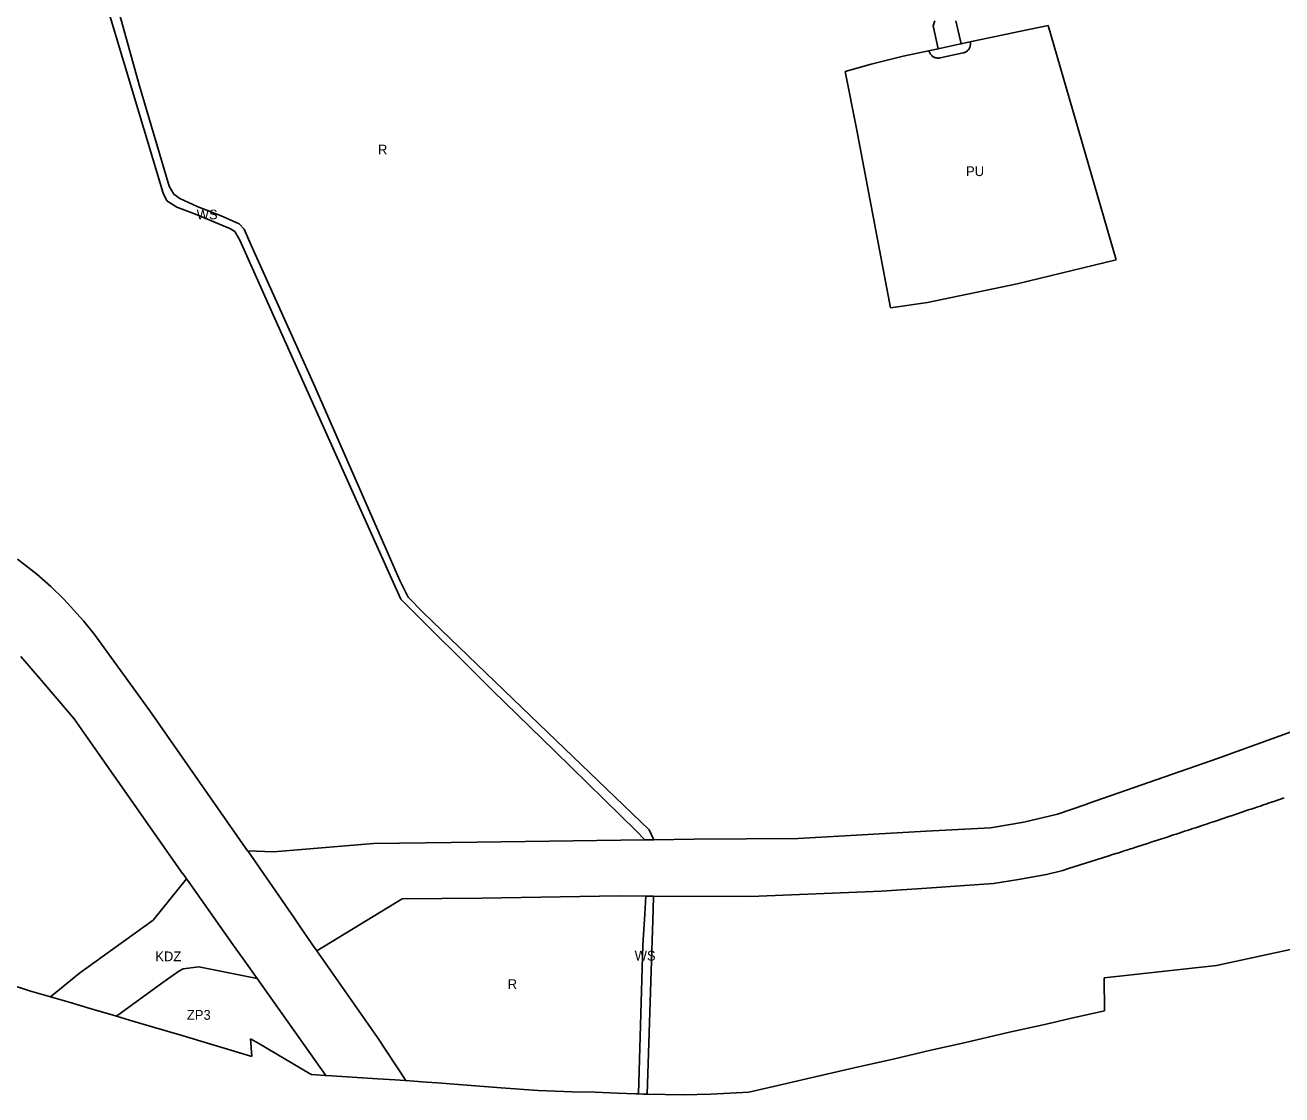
# Model space of a CAD drawing. Extents: x 7435758 to 7439981, y 5550649 to 5554049.
# Drawn here: x 7436435 to 7437107, y 5550649 to 5551221 of the extents above; entities that cross this region are included whole.
import ezdxf

# ---------------------------------------------------------------- set-up
doc = ezdxf.new("R2010")
doc.units = 0
for name, color, linetype in [('linie_rozgraniczające', 7, 'Continuous'), ('linie_zabudowy_nieprzekraczalne', 7, 'Continuous'), ('oznaczenia_przeznaczen', 7, 'Continuous')]:
    doc.layers.add(name, color=color, linetype=linetype)

msp = doc.modelspace()

# ---------------------------------------------------------------- linework, layer by layer
at = {"layer": 'linie_rozgraniczające'}
for p, q in [((7436459.7, 5551296.03), (7436509.03, 5551131.65)), ((7436496.23, 5551189.45), (7436466.37, 5551297.54)), ((7436921.72, 5551223.76), (7436920.85, 5551220.99)), ((7436935.81, 5551211.44), (7436933.05, 5551223.72)), ((7436920.85, 5551220.99), (7436923.56, 5551208.82)), ((7436967.82, 5551218.31), (7436938.84, 5551212.09)), ((7436982.44, 5551221.26), (7436967.82, 5551218.31)), ((7437018.71, 5551095.99), (7436982.44, 5551221.26)), ((7436923.56, 5551208.82), (7436904.82, 5551204.81)), ((7436923.56, 5551208.82), (7436923.98, 5551208.91)), ((7436923.98, 5551208.91), (7436925.08, 5551209.15)), ((7436925.08, 5551209.15), (7436926.84, 5551209.52)), ((7436926.84, 5551209.52), (7436934.77, 5551211.22)), ((7436934.77, 5551211.22), (7436935.81, 5551211.44)), ((7436936.37, 5551211.56), (7436935.81, 5551211.44)), ((7436938.84, 5551212.09), (7436936.37, 5551211.56)), ((7436901.89, 5551204.18), (7436887.77, 5551200.6)), ((7436904.82, 5551204.81), (7436901.89, 5551204.18)), ((7436887.77, 5551200.6), (7436873.73, 5551196.68)), ((7436873.73, 5551196.68), (7436879.85, 5551166.15)), ((7436512.13, 5551135.3), (7436496.23, 5551189.45)), ((7436879.85, 5551166.15), (7436898.01, 5551070.33)), ((7436514.79, 5551131.05), (7436512.13, 5551135.3)), ((7436509.03, 5551131.65), (7436510.99, 5551127.57)), ((7436510.99, 5551127.57), (7436516.32, 5551124.05)), ((7436518, 5551128.69), (7436514.79, 5551131.05)), ((7436527.1, 5551124.49), (7436518, 5551128.69)), ((7436516.32, 5551124.05), (7436526.23, 5551120.3)), ((7436539.96, 5551119.51), (7436527.1, 5551124.49)), ((7436526.23, 5551120.3), (7436544.6, 5551112.64)), ((7436549.69, 5551115.13), (7436539.96, 5551119.51)), ((7436552.29, 5551112.33), (7436549.69, 5551115.13)), ((7436544.6, 5551112.64), (7436547.36, 5551111.09)), ((7436547.36, 5551111.09), (7436550.04, 5551106.43)), ((7436555.95, 5551104.07), (7436552.29, 5551112.33)), ((7436550.04, 5551106.43), (7436567.16, 5551068.1)), ((7436589.47, 5551029.78), (7436555.95, 5551104.07)), ((7436965.75, 5551083.06), (7437018.71, 5551095.99)), ((7436917.85, 5551073.13), (7436965.75, 5551083.06)), ((7436567.16, 5551068.1), (7436595.91, 5551004.2)), ((7436898.01, 5551070.33), (7436917.85, 5551073.13)), ((7436623.1, 5550953), (7436589.47, 5551029.78)), ((7436595.91, 5551004.2), (7436631.06, 5550925.61)), ((7436635.68, 5550924.45), (7436623.1, 5550953)), ((7436431, 5550935.96), (7436441.38, 5550927.82)), ((7436441.38, 5550927.82), (7436448.86, 5550921.33)), ((7436448.86, 5550921.33), (7436455.79, 5550914.51)), ((7436631.06, 5550925.61), (7436636.08, 5550914.4)), ((7436639.98, 5550915.49), (7436635.68, 5550924.45)), ((7436455.79, 5550914.51), (7436466.44, 5550902.86)), ((7436636.08, 5550914.4), (7436685.18, 5550865.64)), ((7436648.21, 5550907.1), (7436639.98, 5550915.49)), ((7436705.45, 5550852.04), (7436648.21, 5550907.1)), ((7436466.44, 5550902.86), (7436472.26, 5550895.52)), ((7436472.26, 5550895.52), (7436501.9, 5550854.69)), ((7436443.93, 5550871.08), (7436432.85, 5550883.86)), ((7436461.44, 5550850.41), (7436443.93, 5550871.08)), ((7436685.18, 5550865.64), (7436718.46, 5550833.16)), ((7436501.9, 5550854.69), (7436554.03, 5550779.92)), ((7436768.94, 5550791.2), (7436705.45, 5550852.04)), ((7437148.56, 5550856.57), (7437073.01, 5550829.36)), ((7436473.84, 5550832.63), (7436461.44, 5550850.41)), ((7436484.73, 5550817.12), (7436473.84, 5550832.63)), ((7436718.46, 5550833.16), (7436762.12, 5550790.41)), ((7437073.01, 5550829.36), (7437003.86, 5550805.18)), ((7436519.37, 5550767.78), (7436484.73, 5550817.12)), ((7437003.86, 5550805.18), (7437002.47, 5550804.74)), ((7437097.01, 5550804.3), (7437099.33, 5550805.09)), ((7437099.33, 5550805.09), (7437100.05, 5550805.33)), ((7437100.05, 5550805.33), (7437102.43, 5550806.14)), ((7437102.43, 5550806.14), (7437103.1, 5550806.37)), ((7437103.1, 5550806.37), (7437105.53, 5550807.21)), ((7437105.53, 5550807.21), (7437106.15, 5550807.42)), ((7437106.15, 5550807.42), (7437108.65, 5550808.27)), ((7436987.39, 5550799.52), (7436969.37, 5550795.22)), ((7437002.47, 5550804.74), (7436987.39, 5550799.52)), ((7437077.88, 5550797.83), (7437078.97, 5550798.2)), ((7437078.97, 5550798.2), (7437080.92, 5550798.85)), ((7437080.92, 5550798.85), (7437081.96, 5550799.2)), ((7437081.96, 5550799.2), (7437083.96, 5550799.88)), ((7437083.96, 5550799.88), (7437084.95, 5550800.21)), ((7437084.95, 5550800.21), (7437087.02, 5550800.91)), ((7437087.02, 5550800.91), (7437087.95, 5550801.23)), ((7437087.95, 5550801.23), (7437090.08, 5550801.94)), ((7437090.08, 5550801.94), (7437090.97, 5550802.24)), ((7437090.97, 5550802.24), (7437093.15, 5550802.99)), ((7437093.15, 5550802.99), (7437093.99, 5550803.27)), ((7437093.99, 5550803.27), (7437096.24, 5550804.03)), ((7437096.24, 5550804.03), (7437097.01, 5550804.3)), ((7436951.63, 5550792.22), (7436917.11, 5550790.34)), ((7436969.37, 5550795.22), (7436951.63, 5550792.22)), ((7437058.27, 5550791.3), (7437059.81, 5550791.81)), ((7437059.81, 5550791.81), (7437061.21, 5550792.27)), ((7437061.21, 5550792.27), (7437062.8, 5550792.8)), ((7437062.8, 5550792.8), (7437064.15, 5550793.25)), ((7437064.15, 5550793.25), (7437065.8, 5550793.8)), ((7437065.8, 5550793.8), (7437067.1, 5550794.23)), ((7437067.1, 5550794.23), (7437068.81, 5550794.8)), ((7437068.81, 5550794.8), (7437070.06, 5550795.22)), ((7437070.06, 5550795.22), (7437071.82, 5550795.8)), ((7437071.82, 5550795.8), (7437073.02, 5550796.2)), ((7437073.02, 5550796.2), (7437074.85, 5550796.81)), ((7437074.85, 5550796.81), (7437075.99, 5550797.2)), ((7437075.99, 5550797.2), (7437077.88, 5550797.83)), ((7436766.65, 5550785.74), (7436676.99, 5550784.49)), ((7436762.12, 5550790.41), (7436766.65, 5550785.74)), ((7436766.65, 5550785.74), (7436771.44, 5550785.81)), ((7436771.44, 5550785.81), (7436768.94, 5550791.2)), ((7436793.04, 5550786.11), (7436771.44, 5550785.81)), ((7436848.73, 5550786.59), (7436793.04, 5550786.11)), ((7436917.11, 5550790.34), (7436848.73, 5550786.59)), ((7437036.12, 5550784.05), (7437037.92, 5550784.64)), ((7437037.92, 5550784.64), (7437039.06, 5550785.01)), ((7437039.06, 5550785.01), (7437040.81, 5550785.58)), ((7437040.81, 5550785.58), (7437042, 5550785.97)), ((7437042, 5550785.97), (7437043.7, 5550786.52)), ((7437043.7, 5550786.52), (7437044.95, 5550786.93)), ((7437044.95, 5550786.93), (7437046.6, 5550787.47)), ((7437046.6, 5550787.47), (7437047.91, 5550787.9)), ((7437047.91, 5550787.9), (7437049.51, 5550788.42)), ((7437049.51, 5550788.42), (7437050.87, 5550788.87)), ((7437050.87, 5550788.87), (7437052.42, 5550789.38)), ((7437052.42, 5550789.38), (7437053.84, 5550789.84)), ((7437053.84, 5550789.84), (7437055.35, 5550790.34)), ((7437055.35, 5550790.34), (7437056.82, 5550790.82)), ((7437056.82, 5550790.82), (7437058.27, 5550791.3)), ((7436554.03, 5550779.92), (7436554.37, 5550779.91)), ((7436554.37, 5550779.91), (7436554.36, 5550779.86)), ((7436554.36, 5550779.86), (7436579.12, 5550744.04)), ((7436568.1, 5550779.29), (7436554.37, 5550779.91)), ((7436621.47, 5550783.86), (7436568.1, 5550779.29)), ((7436676.99, 5550784.49), (7436621.47, 5550783.86)), ((7437015.75, 5550777.51), (7437018.64, 5550778.43)), ((7437018.64, 5550778.43), (7437019.63, 5550778.74)), ((7437019.63, 5550778.74), (7437021.54, 5550779.36)), ((7437021.54, 5550779.36), (7437023.58, 5550780.01)), ((7437023.58, 5550780.01), (7437024.44, 5550780.29)), ((7437024.44, 5550780.29), (7437026.43, 5550780.93)), ((7437026.43, 5550780.93), (7437027.35, 5550781.22)), ((7437027.35, 5550781.22), (7437029.3, 5550781.85)), ((7437029.3, 5550781.85), (7437030.27, 5550782.16)), ((7437030.27, 5550782.16), (7437032.17, 5550782.77)), ((7437032.17, 5550782.77), (7437033.19, 5550783.11)), ((7437033.19, 5550783.11), (7437035.04, 5550783.7)), ((7437035.04, 5550783.7), (7437036.12, 5550784.05)), ((7436993.21, 5550770.38), (7437014.36, 5550777.07)), ((7437014.36, 5550777.07), (7437014.91, 5550777.24)), ((7437014.91, 5550777.24), (7437015.46, 5550777.42)), ((7437015.46, 5550777.42), (7437015.72, 5550777.5)), ((7437015.72, 5550777.5), (7437015.75, 5550777.51)), ((7436521.56, 5550764.97), (7436503.68, 5550742.8)), ((7436519.57, 5550767.79), (7436519.37, 5550767.78)), ((7436521.56, 5550764.97), (7436519.57, 5550767.79)), ((7436522.05, 5550764.27), (7436521.56, 5550764.97)), ((7436953.09, 5550762.52), (7436966.48, 5550764.65)), ((7436966.48, 5550764.65), (7436981.51, 5550767.19)), ((7436981.51, 5550767.19), (7436990.22, 5550769.43)), ((7436990.22, 5550769.43), (7436993.21, 5550770.38)), ((7436523.85, 5550761.72), (7436522.05, 5550764.27)), ((7436545.1, 5550731.53), (7436523.85, 5550761.72)), ((7436823.12, 5550755.47), (7436893.19, 5550758.31)), ((7436893.19, 5550758.31), (7436917.51, 5550759.89)), ((7436917.51, 5550759.89), (7436953.09, 5550762.52)), ((7436591.13, 5550726.48), (7436636.87, 5550754.2)), ((7436636.87, 5550754.2), (7436679.42, 5550754.59)), ((7436679.42, 5550754.59), (7436752.93, 5550755.79)), ((7436752.93, 5550755.79), (7436767.22, 5550755.72)), ((7436767.22, 5550755.72), (7436766.62, 5550746.07)), ((7436771.2, 5550755.71), (7436767.22, 5550755.72)), ((7436771.09, 5550748.33), (7436771.2, 5550755.71)), ((7436771.2, 5550755.71), (7436823.12, 5550755.47)), ((7436766.62, 5550746.07), (7436765.63, 5550729.42)), ((7436767.84, 5550649.78), (7436771.09, 5550748.33)), ((7436503.68, 5550742.8), (7436471.83, 5550719.96)), ((7436579.12, 5550744.04), (7436579.85, 5550742.98)), ((7436579.85, 5550742.98), (7436582, 5550739.87)), ((7436582, 5550739.87), (7436588.56, 5550730.13)), ((7436546.66, 5550729.32), (7436545.1, 5550731.53)), ((7436547.18, 5550728.58), (7436546.66, 5550729.32)), ((7436552.6, 5550720.95), (7436547.18, 5550728.58)), ((7436588.56, 5550730.13), (7436591.13, 5550726.48)), ((7436591.13, 5550726.48), (7436623.68, 5550680.13)), ((7436765.63, 5550729.42), (7436763.27, 5550649.93)), ((7437126.08, 5550730.18), (7437072.37, 5550718.54)), ((7436471.83, 5550719.96), (7436464.16, 5550714.46)), ((7436528.04, 5550717.83), (7436519.72, 5550716.78)), ((7436559.24, 5550711.59), (7436528.04, 5550717.83)), ((7436559.24, 5550711.59), (7436552.6, 5550720.95)), ((7437072.37, 5550718.54), (7437012.36, 5550711.98)), ((7436464.16, 5550714.46), (7436448.78, 5550701.87)), ((7436517.33, 5550715.54), (7436508.22, 5550709.11)), ((7436519.72, 5550716.78), (7436517.33, 5550715.54)), ((7436596.06, 5550659.71), (7436559.24, 5550711.59)), ((7437012.36, 5550711.98), (7437012.6, 5550694.43)), ((7436437.48, 5550705.09), (7436426.03, 5550708.86)), ((7436448.78, 5550701.87), (7436437.48, 5550705.09)), ((7436508.22, 5550709.11), (7436484.06, 5550691.46)), ((7436458.65, 5550699.06), (7436448.78, 5550701.87)), ((7436470.53, 5550695.46), (7436458.65, 5550699.06)), ((7436482.32, 5550691.97), (7436470.53, 5550695.46)), ((7436484.06, 5550691.46), (7436482.32, 5550691.97)), ((7436491, 5550689.42), (7436484.06, 5550691.46)), ((7436998.96, 5550691.37), (7436994.79, 5550690.4)), ((7437012.6, 5550694.43), (7436998.96, 5550691.37)), ((7436504.36, 5550685.49), (7436491, 5550689.42)), ((7436517.96, 5550681.46), (7436504.36, 5550685.49)), ((7436981.27, 5550687.24), (7436960.14, 5550682.66)), ((7436994.79, 5550690.4), (7436981.27, 5550687.24)), ((7436556.42, 5550670.02), (7436517.96, 5550681.46)), ((7436560.24, 5550676.84), (7436555.66, 5550679.37)), ((7436555.66, 5550679.37), (7436556.42, 5550670.02)), ((7436623.68, 5550680.13), (7436638.75, 5550657.08)), ((7436937.4, 5550677.32), (7436919.6, 5550673.24)), ((7436960.14, 5550682.66), (7436937.4, 5550677.32)), ((7436587.3, 5550660.9), (7436560.24, 5550676.84)), ((7436919.6, 5550673.24), (7436899.53, 5550668.59)), ((7436880.99, 5550664.38), (7436853.13, 5550657.96)), ((7436899.53, 5550668.59), (7436880.99, 5550664.38)), ((7436588.27, 5550660.33), (7436587.3, 5550660.9)), ((7436595.74, 5550659.73), (7436588.27, 5550660.33)), ((7436596.06, 5550659.71), (7436595.74, 5550659.73)), ((7436599.21, 5550659.58), (7436596.06, 5550659.71)), ((7436623.56, 5550658.05), (7436599.21, 5550659.58)), ((7436633.12, 5550657.46), (7436623.56, 5550658.05)), ((7436638.52, 5550657.1), (7436633.12, 5550657.46)), ((7436638.75, 5550657.08), (7436638.52, 5550657.1)), ((7436643.09, 5550656.7), (7436638.75, 5550657.08)), ((7436853.13, 5550657.96), (7436840.19, 5550654.99)), ((7436649.83, 5550656.19), (7436643.09, 5550656.7)), ((7436655.54, 5550655.77), (7436649.83, 5550656.19)), ((7436689.81, 5550653.16), (7436655.54, 5550655.77)), ((7436709.52, 5550651.69), (7436689.81, 5550653.16)), ((7436727.81, 5550651.09), (7436709.52, 5550651.69)), ((7436740.02, 5550650.86), (7436727.81, 5550651.09)), ((7436751.77, 5550650.28), (7436740.02, 5550650.86)), ((7436762.02, 5550649.99), (7436751.77, 5550650.28)), ((7436822.3, 5550650.94), (7436801.97, 5550649.86)), ((7436840.19, 5550654.99), (7436822.3, 5550650.94)), ((7436763.27, 5550649.93), (7436762.02, 5550649.99)), ((7436765.92, 5550649.81), (7436763.27, 5550649.93)), ((7436767.84, 5550649.78), (7436765.92, 5550649.81)), ((7436787.23, 5550649.42), (7436767.84, 5550649.78)), ((7436801.97, 5550649.86), (7436787.23, 5550649.42))]:
    msp.add_line(p, q, dxfattribs=at)
at = {"layer": 'linie_zabudowy_nieprzekraczalne'}
msp.add_lwpolyline([(7436940.7, 5551212.46), (7436940.74, 5551212.3), (7436940.78, 5551211.97), (7436940.81, 5551211.65), (7436940.81, 5551211.32), (7436940.79, 5551210.99), (7436940.75, 5551210.67), (7436940.69, 5551210.35), (7436940.61, 5551210.03), (7436940.5, 5551209.72), (7436940.38, 5551209.42), (7436940.24, 5551209.12), (7436940.08, 5551208.84), (7436939.9, 5551208.56), (7436939.7, 5551208.3), (7436939.49, 5551208.05), (7436939.26, 5551207.82), (7436939.01, 5551207.6), (7436938.75, 5551207.4), (7436938.48, 5551207.22), (7436938.2, 5551207.05), (7436937.91, 5551206.91), (7436937.61, 5551206.78), (7436937.3, 5551206.67), (7436936.98, 5551206.58), (7436936.86, 5551206.55), (7436924.61, 5551203.93), (7436924.41, 5551203.89), (7436924.09, 5551203.85), (7436923.76, 5551203.82), (7436923.43, 5551203.82), (7436923.11, 5551203.84), (7436922.78, 5551203.88), (7436922.46, 5551203.94), (7436922.14, 5551204.02), (7436921.83, 5551204.13), (7436921.53, 5551204.25), (7436921.24, 5551204.39), (7436920.95, 5551204.55), (7436920.68, 5551204.73), (7436920.42, 5551204.93), (7436920.17, 5551205.14), (7436919.94, 5551205.37), (7436919.72, 5551205.62), (7436919.52, 5551205.88), (7436919.33, 5551206.15), (7436919.17, 5551206.43), (7436919.02, 5551206.72), (7436918.89, 5551207.02), (7436918.79, 5551207.33), (7436918.7, 5551207.65), (7436918.68, 5551207.73), (7436918.67, 5551207.78)], dxfattribs=at)

# ---------------------------------------------------------------- texts
at = {"layer": 'oznaczenia_przeznaczen'}
for s, p in [('R', (7436623.88, 5551152.32)), ('PU', (7436938.46, 5551140.73)), ('WS', (7436526.91, 5551117.59)), ('KDZ', (7436504.76, 5550720.88)), ('WS', (7436761.21, 5550721.24)), ('R', (7436693.29, 5550706.04)), ('ZP3', (7436521.66, 5550689.58))]:
    msp.add_text(s, height=5.2, dxfattribs=at).set_placement(p)

doc.saveas('drawing.dxf')
